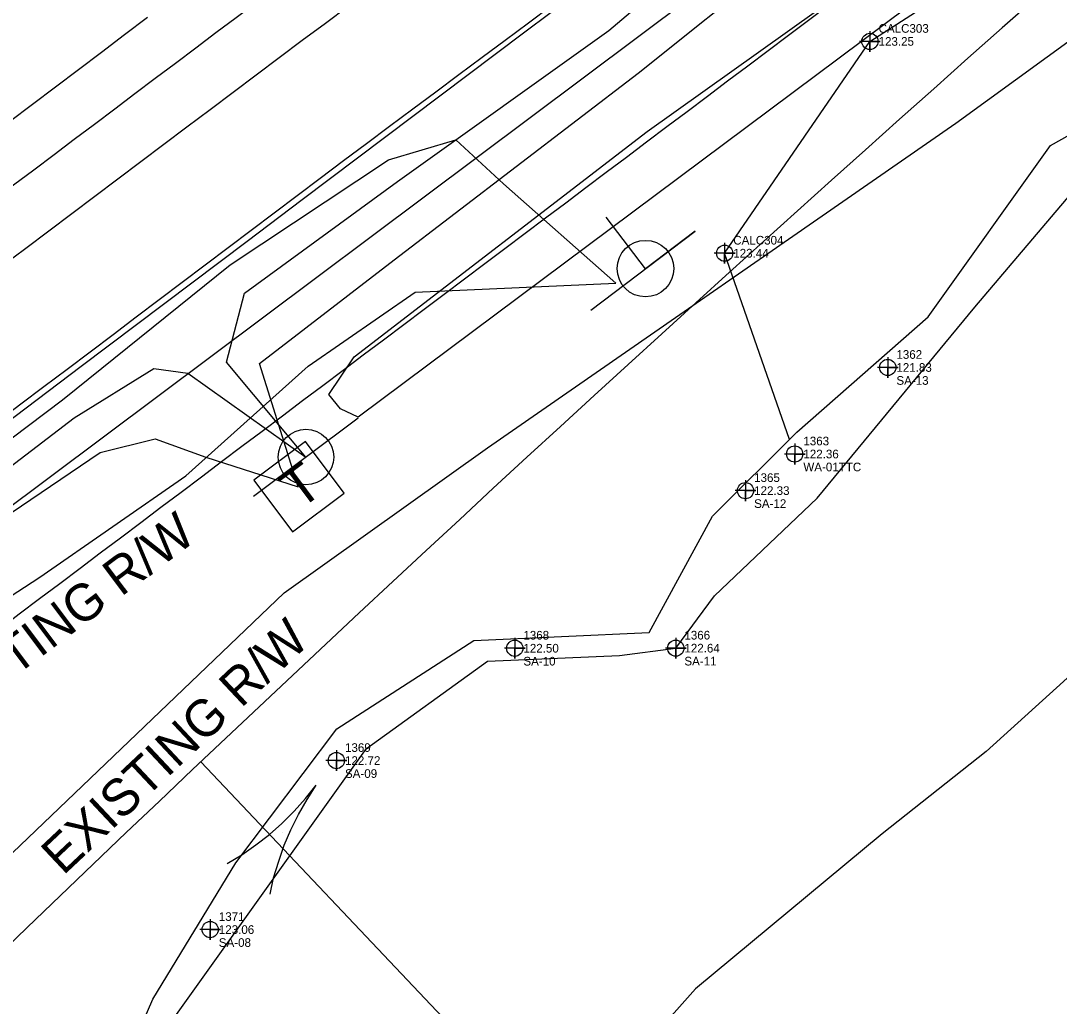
# Model space of a CAD drawing. Extents: x 2186615 to 2188822, y 629899 to 631820.
# Drawn here: x 2187024.7 to 2187114.7, y 630222.6 to 630308 of the extents above; entities that cross this region are included whole.
import ezdxf

# ---------------------------------------------------------------- set-up
doc = ezdxf.new("R2010")
doc.units = 0
for name, color, linetype in [('Exist Environmental Wetland Boundary', 7, 'Continuous'), ('Exist Environmental Wetland Boundary Cogo Comment', 7, 'Continuous'), ('Exist Environmental Wetland Boundary Cogo Elevation', 7, 'Continuous'), ('Exist Environmental Wetland Boundary Cogo Number', 7, 'Continuous'), ('Exist Environmental Wetland Boundary Cogo Point CELL', 7, 'Continuous'), ('Exist Horizontal Alignment', 7, 'Continuous'), ('Exist Hydro Jurisdictional Stream or Body of Water', 7, 'Continuous'), ('Exist Hydro Stream Flow Arrow CELL', 7, 'Continuous'), ('Exist Right of Way Line', 7, 'Continuous'), ('Exist Right of Way Line Text', 7, 'Continuous'), ('Exist Right of Way Width CELL', 7, 'Continuous'), ('Exist Roads EOP', 7, 'Continuous'), ('Exist Roads EOT', 7, 'Continuous'), ('Exist Utilities Power Joint Use Telephone CELL', 7, 'Continuous'), ('Exist Utilities Sanitary Sewer UG Line', 7, 'Continuous'), ('Exist Utilities Telephone Pedestal CELL', 7, 'Continuous'), ('Exist Utilities Telephone Pole CELL', 7, 'Continuous'), ('Exist Utilities Telephone UG Cable SUE LOS C', 7, 'Continuous'), ('Exist Utilities Telephone UG FO SUE LOS B', 7, 'Continuous'), ('Exist Vegetation Woods Line', 7, 'Continuous'), ('Scratch_Level_1', 7, 'Continuous')]:
    doc.layers.add(name, color=color, linetype=linetype)

msp = doc.modelspace()

# ---------------------------------------------------------------- linework, layer by layer
at = {"layer": 'Exist Environmental Wetland Boundary'}
msp.add_lwpolyline([(2187091.311, 630271.672), (2187085.676, 630287.812), (2187098.271, 630306.167), (2187117.246, 630318.391), (2187145.167, 630331.818), (2187167.383, 630352.861), (2187202.427, 630381.298), (2187228.671, 630401.09), (2187258.21, 630420.516), (2187282.166, 630435.853)], dxfattribs=at)
at = {"layer": 'Exist Environmental Wetland Boundary Cogo Point CELL'}
for points in [[(2187098.271, 630307.067), (2187098.271, 630305.267), (2187098.271, 630306.167), (2187099.171, 630306.167), (2187097.371, 630306.167)], [(2187085.676, 630288.712), (2187085.676, 630286.912), (2187085.676, 630287.812), (2187086.576, 630287.812), (2187084.776, 630287.812)], [(2187099.815, 630278.81), (2187099.815, 630277.01), (2187099.815, 630277.91), (2187100.715, 630277.91), (2187098.915, 630277.91)], [(2187091.751, 630271.311), (2187091.751, 630269.511), (2187091.751, 630270.411), (2187092.651, 630270.411), (2187090.851, 630270.411)], [(2187087.483, 630268.138), (2187087.483, 630266.338), (2187087.483, 630267.238), (2187088.383, 630267.238), (2187086.583, 630267.238)], [(2187067.482, 630254.48), (2187067.482, 630252.68), (2187067.482, 630253.58), (2187068.382, 630253.58), (2187066.582, 630253.58)], [(2187081.437, 630254.485), (2187081.437, 630252.685), (2187081.437, 630253.585), (2187082.337, 630253.585), (2187080.537, 630253.585)], [(2187052.019, 630244.744), (2187052.019, 630242.944), (2187052.019, 630243.844), (2187052.919, 630243.844), (2187051.119, 630243.844)], [(2187041.081, 630230.098), (2187041.081, 630228.298), (2187041.081, 630229.198), (2187041.981, 630229.198), (2187040.181, 630229.198)]]:
    msp.add_lwpolyline(points, dxfattribs=at)
for centre in [(2187098.271, 630306.167), (2187085.676, 630287.812), (2187099.815, 630277.91), (2187091.751, 630270.411), (2187087.483, 630267.238), (2187067.482, 630253.58), (2187081.437, 630253.585), (2187052.019, 630243.844), (2187041.081, 630229.198)]:
    msp.add_circle(centre, 0.703, dxfattribs=at)
at = {"layer": 'Exist Horizontal Alignment'}
msp.add_arc((2232330.704, 570095.737), 75342.476, 126.85926308, 127.07301977, dxfattribs=at)
at = {"layer": 'Exist Hydro Jurisdictional Stream or Body of Water'}
for points in [[(2186945.282, 630142.135), (2186953.45, 630139.974), (2186959.365, 630142.562), (2186957.754, 630149), (2186960.653, 630154.127), (2186970.578, 630158.18), (2186979.2, 630165.074), (2186985.237, 630175.204), (2186992.204, 630182.179), (2187005.048, 630185.832), (2187012.272, 630196.734), (2187018.23, 630207.265), (2187030.87, 630211.07), (2187036.119, 630223.159), (2187043.302, 630234.994), (2187052.049, 630246.593), (2187063.942, 630254.242), (2187079.125, 630254.944), (2187084.623, 630265.035), (2187091.947, 630272.303), (2187103.314, 630282.286), (2187113.925, 630297.142), (2187128.079, 630305.06)], [(2187038.168, 630221.845), (2187054.629, 630244.885), (2187065.118, 630252.467), (2187076.564, 630252.95), (2187081.437, 630253.585), (2187084.791, 630258.118), (2187093.684, 630266.574), (2187107.375, 630283.147), (2187119.04, 630296.895)]]:
    msp.add_lwpolyline(points, dxfattribs=at)
at = {"layer": 'Exist Hydro Stream Flow Arrow CELL'}
msp.add_line((2187047.346, 630237.647), (2187047.346, 630237.647), dxfattribs=at)
for points in [[(2187042.567, 630234.928), (2187043.836, 630235.662), (2187045.044, 630236.548), (2187046.225, 630237.438), (2187047.304, 630238.402), (2187048.352, 630239.45), (2187049.353, 630240.561), (2187050.269, 630241.704)], [(2187046.279, 630232.254), (2187046.574, 630233.689), (2187047.032, 630235.116), (2187047.502, 630236.518), (2187048.075, 630237.846), (2187048.737, 630239.172), (2187049.475, 630240.474), (2187050.269, 630241.704)]]:
    msp.add_lwpolyline(points, dxfattribs=at)
at = {"layer": 'Exist Right of Way Line'}
for centre, radius, start, end in [((2189028.8, 628141.736), 2893.554, 125.65722, 135.708207), ((2232330.704, 570095.737), 75372.476, 126.85926308, 127.07301977), ((2189028.8, 628141.736), 2763.554, 125.65722, 135.708207), ((2232330.704, 570095.737), 75312.476, 126.85926308, 127.07301977)]:
    msp.add_arc(centre, radius, start, end, dxfattribs=at)
at = {"layer": 'Exist Right of Way Width CELL'}
msp.add_line((2187040.283, 630243.749), (2187087.534, 630193.801), dxfattribs=at)
at = {"layer": 'Exist Roads EOP'}
msp.add_lwpolyline([(2187073.032, 630310.488), (2187068.238, 630306.881), (2187063.444, 630303.273), (2187058.652, 630299.663), (2187053.861, 630296.052), (2187049.069, 630292.441), (2187044.278, 630288.83), (2187039.487, 630285.219), (2187034.697, 630281.607), (2187029.909, 630277.993), (2187025.121, 630274.377), (2187020.333, 630270.762)], dxfattribs=at)
at = {"layer": 'Exist Roads EOT'}
for points in [[(2187070.669, 630309.244), (2187068.663, 630307.752), (2187066.658, 630306.259), (2187064.653, 630304.767), (2187062.647, 630303.274), (2187060.642, 630301.782), (2187058.636, 630300.289), (2187056.631, 630298.797), (2187054.626, 630297.303), (2187052.626, 630295.804), (2187050.63, 630294.299), (2187048.634, 630292.793), (2187046.638, 630291.288), (2187044.643, 630289.782), (2187042.647, 630288.277), (2187040.652, 630286.772), (2187038.656, 630285.266), (2187036.661, 630283.761), (2187034.664, 630282.256), (2187032.668, 630280.752), (2187030.671, 630279.248), (2187028.674, 630277.745), (2187026.677, 630276.241), (2187024.681, 630274.737), (2187022.684, 630273.233)], [(2187023.093, 630286.74), (2187025.09, 630288.243), (2187027.087, 630289.746), (2187029.084, 630291.249), (2187031.082, 630292.752), (2187033.079, 630294.255), (2187035.076, 630295.758), (2187037.073, 630297.262), (2187039.071, 630298.765), (2187041.069, 630300.267), (2187043.068, 630301.768), (2187045.068, 630303.267), (2187047.069, 630304.766), (2187049.07, 630306.264), (2187051.071, 630307.762), (2187053.072, 630309.261)], [(2187023.695, 630299.222), (2187025.689, 630300.729), (2187027.684, 630302.235), (2187029.678, 630303.742), (2187031.673, 630305.248), (2187033.668, 630306.754), (2187035.663, 630308.261)]]:
    msp.add_lwpolyline(points, dxfattribs=at)
at = {"layer": 'Exist Utilities Power Joint Use Telephone CELL'}
msp.add_line((2187078.812, 630286.47), (2187078.812, 630286.47), dxfattribs=at)
msp.add_lwpolyline([(2187074.086, 630282.875), (2187083.133, 630289.709), (2187078.824, 630286.454), (2187075.407, 630290.947)], dxfattribs=at)
msp.add_circle((2187078.809, 630286.476), 2.45, dxfattribs=at)
at = {"layer": 'Exist Utilities Sanitary Sewer UG Line'}
msp.add_line((2186953.526, 630213.342), (2187280.261, 630457.751), dxfattribs=at)
at = {"layer": 'Exist Utilities Telephone Pedestal CELL'}
msp.add_line((2187048.711, 630267.562), (2187048.711, 630267.562), dxfattribs=at)
msp.add_lwpolyline([(2187048.215, 630263.668), (2187052.701, 630267.01), (2187049.359, 630271.497), (2187044.873, 630268.155), (2187048.215, 630263.668)], dxfattribs=at)
at = {"layer": 'Exist Utilities Telephone Pole CELL'}
for p, q in [((2187044.842, 630266.744), (2187053.917, 630273.539)), ((2187049.385, 630270.146), (2187049.385, 630270.146))]:
    msp.add_line(p, q, dxfattribs=at)
msp.add_circle((2187049.385, 630270.146), 2.407, dxfattribs=at)
at = {"layer": 'Exist Utilities Telephone UG Cable SUE LOS C'}
for points in [[(2187048.711, 630267.562), (2187045.354, 630278.254), (2187057.018, 630287.248), (2187078.192, 630303.416), (2187102.037, 630322.514), (2187119.945, 630336.137), (2187137.937, 630349.883), (2187161.709, 630367.862), (2187186.024, 630384.639), (2187207.077, 630401.804), (2187231.599, 630419.787), (2187256.848, 630438.711), (2187278.852, 630453.798), (2187296.978, 630467.542), (2187304.942, 630472.732), (2187317.617, 630478.554), (2187327.51, 630484.53), (2187332.683, 630485.862), (2187337.992, 630482.804), (2187346.28, 630476.796)], [(2186993.862, 630234.892), (2187014.015, 630251.722), (2187026.326, 630259.734), (2187038.967, 630268.514), (2187049.587, 630278.035), (2187058.856, 630284.432), (2187076.233, 630285.219)], [(2186988.908, 630240.518), (2187010.986, 630256.618), (2187031.554, 630270.541), (2187036.316, 630271.727), (2187040.709, 630270.129), (2187048.711, 630267.562)]]:
    msp.add_lwpolyline(points, dxfattribs=at)
at = {"layer": 'Exist Utilities Telephone UG FO SUE LOS B'}
for points in [[(2187049.385, 630270.146), (2187042.504, 630278.367), (2187044.061, 630284.337), (2187057.315, 630294.022), (2187075.644, 630307.116), (2187098.729, 630326.668), (2187116.947, 630341.492), (2187134.442, 630355.423), (2187157.809, 630373.051), (2187181.899, 630390.785), (2187205.122, 630408.701), (2187231.973, 630429.319), (2187252.444, 630444.703), (2187272.54, 630459.689), (2187294.094, 630476.316), (2187309.645, 630487.965), (2187327.188, 630501.034), (2187332.668, 630500.224), (2187340.344, 630491.389), (2187346.28, 630476.796)], [(2186986.295, 630243.894), (2187007.861, 630259.716), (2187028.276, 630275.112), (2187042.806, 630286.802), (2187056.536, 630295.904), (2187062.362, 630297.624), (2187066.496, 630293.81), (2187076.233, 630285.219)], [(2186987.506, 630242.361), (2187009.305, 630258.272), (2187029.28, 630273.535), (2187036.206, 630277.824), (2187039.143, 630277.431), (2187049.385, 630270.146)]]:
    msp.add_lwpolyline(points, dxfattribs=at)
at = {"layer": 'Exist Vegetation Woods Line'}
msp.add_line((2187065.129, 630270.937), (2187105.726, 630299.086), dxfattribs=at)
for points in [[(2187105.726, 630299.086), (2187150.799, 630331.829), (2187206.105, 630372.034), (2187256.074, 630407.258), (2187300.913, 630439.289), (2187349.475, 630473.877), (2187396.874, 630507.865), (2187440.691, 630538.214), (2187466.075, 630555.071), (2187474.722, 630557.755), (2187481.166, 630558.923), (2187486.051, 630559.676), (2187489.303, 630561.136), (2187491.384, 630563.953), (2187492.451, 630570.166), (2187494.251, 630572.315)], [(2187105.521, 630312.125), (2187053.915, 630273.616), (2187052.393, 630274.331), (2187051.38, 630275.579), (2187053.558, 630278.826), (2187078.954, 630298.348), (2187103.491, 630315.876)], [(2187134.591, 630271.745), (2187127.093, 630263.839), (2187118.716, 630254.032), (2187108.354, 630244.627), (2187099.339, 630237.488), (2187083.149, 630224.071), (2187071.543, 630211.013), (2187060.061, 630197.378), (2187049.397, 630179.92), (2187044.567, 630174.225), (2187039.186, 630171.313), (2187034.501, 630168.824), (2187030.703, 630164.511), (2187029.133, 630160.783), (2187025.281, 630155.531), (2187015.338, 630148.081), (2187000.995, 630138.025), (2186990.129, 630132.3), (2186985.298, 630118.088)], [(2186944.379, 630160.412), (2186956.197, 630164.929), (2186962.271, 630168.27), (2186984.343, 630188.213), (2187009.886, 630214.679), (2187023.297, 630235.224), (2187047.498, 630258.381), (2187065.129, 630270.937)]]:
    msp.add_lwpolyline(points, dxfattribs=at)
at = {"layer": 'Scratch_Level_1'}
msp.add_arc((2189028.8, 628141.736), 2815.554, 125.65722, 135.708207, dxfattribs=at)

# ---------------------------------------------------------------- texts
at = {"layer": 'Exist Environmental Wetland Boundary Cogo Comment'}
for s, p in [('SA-13', (2187100.565, 630276.41)), ('WA-01TTC', (2187092.501, 630268.911)), ('SA-12', (2187088.233, 630265.738)), ('SA-10', (2187068.232, 630252.08)), ('SA-11', (2187082.187, 630252.085)), ('SA-09', (2187052.769, 630242.344)), ('SA-08', (2187041.831, 630227.698))]:
    msp.add_text(s, height=0.75, dxfattribs=at).set_placement(p)
at = {"layer": 'Exist Environmental Wetland Boundary Cogo Elevation'}
for s, p in [('123.25', (2187099.021, 630305.792)), ('123.44', (2187086.426, 630287.437)), ('121.83', (2187100.565, 630277.535)), ('122.36', (2187092.501, 630270.036)), ('122.33', (2187088.233, 630266.863)), ('122.50', (2187068.232, 630253.205)), ('122.64', (2187082.187, 630253.21)), ('122.72', (2187052.769, 630243.469)), ('123.06', (2187041.831, 630228.823))]:
    msp.add_text(s, height=0.75, dxfattribs=at).set_placement(p)
at = {"layer": 'Exist Environmental Wetland Boundary Cogo Number'}
for s, p in [('CALC303', (2187099.021, 630306.917)), ('CALC304', (2187086.426, 630288.562)), ('1362', (2187100.565, 630278.66)), ('1363', (2187092.501, 630271.161)), ('1365', (2187088.233, 630267.988)), ('1368', (2187068.232, 630254.33)), ('1366', (2187082.187, 630254.335)), ('1369', (2187052.769, 630244.594)), ('1371', (2187041.831, 630229.948))]:
    msp.add_text(s, height=0.75, dxfattribs=at).set_placement(p)
at = {"layer": 'Exist Right of Way Line Text'}
for rotation, p in [(36.89538, (2187016.429, 630245.292)), (43.24766, (2187028.339, 630233.835))]:
    msp.add_text('EXISTING R/W', height=3.2, rotation=rotation, dxfattribs=at).set_placement(p)
at = {"layer": 'Exist Utilities Telephone Pedestal CELL'}
msp.add_text('T', height=3.42, rotation=36.6849, dxfattribs=at).set_placement((2187048.828, 630265.512))

doc.saveas('drawing.dxf')
